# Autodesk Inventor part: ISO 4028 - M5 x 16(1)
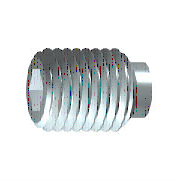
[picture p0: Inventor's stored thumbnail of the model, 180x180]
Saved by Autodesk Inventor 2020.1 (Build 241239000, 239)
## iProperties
Created: 2019-01
Part Number: ISO 4028 - M5 x 16(1)
Material: Edelstahl, 440C
Description: Innensechskant-Gewindestifte mit Zapfen
Document SubType Name: Modeling
Standard: ISO 4028
Designer: lutzd
Standard Revision: Third edition 2003-12-01
Standards Organization: ISO
Language: de-DE
Size Designation: M5 x 16
Categories: <MemberInstance><Categories><Category DisplayName="Verbindungselemente" InternalName="e4da775c-781d-43d5-af7c-5136215cf5a6" Mnemonic="FSTN"><Category DisplayNam
Mass: 2.05665 g
Surface Area: 2.93807 cm^2
Volume: 0.265375 cm^3
Density: 7.75 g/cm^3
Appearance: Halbpoliert
IsCustomPart: 0
Author: lutzd
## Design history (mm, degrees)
sketch "Skizze1"
  geometry: L1 (0, 0)-(12.167, 0); L2 (16, 1.443)-(16, 2.5); L3 (16, 2.5)-(2.5, 2.5); L4 (16, 1.443)-(13, 1.443); L5 (13, 1.443)-(12.167, 0); L6 (0, -0.5)-(0, 3) reference; L7 (0, 1.75)-(0, 0); L8 (0, 1.75)-(2.5, 1.75); L9 (2.5, 1.75)-(2.5, 2.5)
  constraints: 17 end point, 3 parallel, 3 perpendicular, 1 collinear, 1 point on line
  dimensions: "d0" = 3 distance of L2.start L4.end (= INTI); "d1" = 60 deg angle of L5 L1; "d2" = 5 diameter of L3 L1 (= NND); "d3" = 2.88675 diameter of L4 L1 (= 1.1547 x SW); "d5" = 16 distance from line of L2 L7.start (= NLG); "d7" = 3.5 diameter of L7.start L1 (= SPD); "d14" = 2.5 distance of L7.start L8.end (= ZLG)
revolve "Körper" sketch "Skizze1" stored, may be unused: angle "d6" = 90 deg
sketch "Skizze2"
  geometry: L1 (-0.722, 1.25)-(0.722, 1.25); L2 (0.722, 1.25)-(1.443, 0); L3 (1.443, 0)-(0.722, -1.25); L4 (0.722, -1.25)-(-0.722, -1.25); L5 (-0.722, -1.25)-(-1.443, 0); L6 (-1.443, 0)-(-0.722, 1.25); A1 r 1.443 centre (0, 0) between (-0.722, 1.25) and (0.722, 1.25) reference; 2 further points
  constraints: 12 end point, 2 point on circle, 1 coincident, 1 horizontal, 11 other
extrude "Loch" join sketch "Skizze2" taper "d10" = 0 deg; stored distance "d21" = 10
workaxis "Work Axis1"
workplane "Work Plane1"
body "Solid1"
chamfer "Fase1" distance "d8" = 0.49076 (computed from NND, GD1, FAWI); stored, may be unused: angle "d9" = 45 deg (= FAWI), second distance "d30" = 0.49076 (computed from NND, GD1, FAWI)
feature "Gewinde" dims "d12" = 13.5 (= NLG - ZLG), "d13" = 0
chamfer "Fase2" distance "d15" = 0.75 (computed from NND, SPD, FAWI1); stored, may be unused: angle "d16" = 45 deg (= FAWI1), second distance "d31" = 0.75 (computed from NND, SPD, FAWI1)
other parameters: "NND" = 5 [user parameter; used in 5 equation terms], "NLG" = 16 [user parameter; used in 2 equation terms], "INTI" = 3 [user parameter; used in 1 equation term], "FAWI" = 45 deg [user parameter; used in 3 equation terms], "SW" = 2.5 [user parameter; used in 2 equation terms], "GD1" = 4.01848 (= THREADDIA - 1.2269 x PTC) [user parameter; used in 2 equation terms], "d4" = 0, "FAWI1" = 45 deg [user parameter; used in 3 equation terms], "SPD" = 3.5 [user parameter; used in 3 equation terms], "ZLG" = 2.5 [user parameter; used in 2 equation terms], "d32" = 0, "d33" = 0, "GUL" = 0.49076 (= 0.61345 x PTC) [user parameter], "TPU" = 12.5 (computed from PTC) [user parameter], "TOA" = 30 deg [user parameter], "THREADDIA" = 5 [user parameter; used in 1 equation term], "PTC" = 0.8 [user parameter; used in 4 equation terms], "GAL" = 0.49076 (= 0.61345 x PTC) [user parameter], "E0" = 2.8875 (= 1.155 x SW) [user parameter]
